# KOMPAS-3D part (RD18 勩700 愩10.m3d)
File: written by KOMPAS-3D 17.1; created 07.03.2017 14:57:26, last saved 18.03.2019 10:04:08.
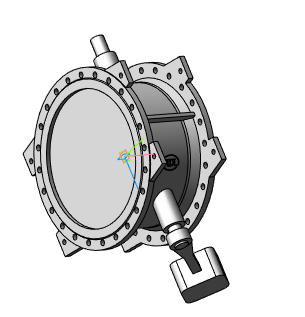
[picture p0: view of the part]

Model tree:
1. Операция без истории:2  (labels: Сталь 20  ГОСТ 1050-88)

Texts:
  RD18 Ду100 Ру16
  RD18 Ду150 Ру16
  RD18 Ду200 Ру16
  RD18 Ду250 Ру16
  RD18 Ду300 Ру16
  RD18 Ду350 Ру16
  RD18 Ду400 Ру10
  RD18 Ду400 Ру16
  RD18 Ду450 Ру10
  RD18 Ду450 Ру16
  RD18 Ду500 Ру10
  RD18 Ду500 Ру16
  RD18 Ду600 Ру10
  RD18 Ду600 Ру16
  RD18 Ду700 Ру10
  RD18 Ду700 Ру16
  RD18 Ду800 Ру10
  RD18 Ду800 Ру16
  RD18 Ду900 Ру10
  RD18 Ду900 Ру16
  RD18 Ду1000 Ру10
  RD18 Ду1000 Ру16
  RD18 Ду1200 Ру16
  RD18 Ду1400 Ру16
